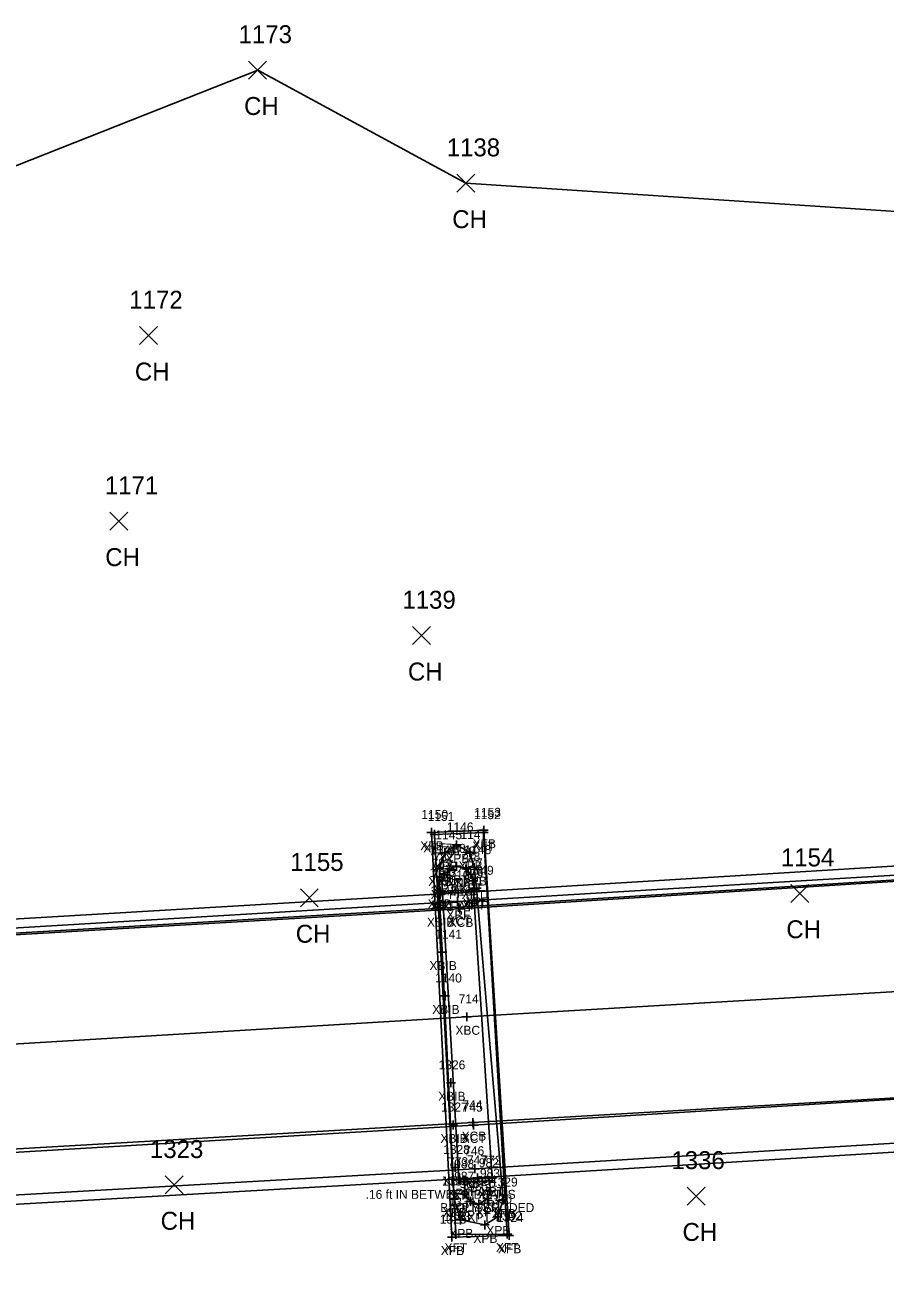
# Model space of a CAD drawing. Extents: x 1715662 to 1717487, y 887396 to 890004.
# Drawn here: x 1717008.3 to 1717104.2, y 888212.7 to 888351.7 of the extents above; entities that cross this region are included whole.
import ezdxf

# ---------------------------------------------------------------- set-up
doc = ezdxf.new("R2010")
doc.units = 0
for name, color, linetype in [('B_A', 7, 'Continuous'), ('B_C', 7, 'Continuous'), ('B_I', 7, 'Continuous'), ('B_TIC', 7, 'Continuous'), ('BDC', 7, 'Continuous'), ('BELB', 7, 'Continuous'), ('BF', 7, 'Continuous'), ('BFT', 7, 'Continuous'), ('BR', 7, 'Continuous'), ('BSUBM', 7, 'Continuous'), ('L_A', 7, 'Continuous'), ('L_I', 7, 'Continuous'), ('L_TIC', 7, 'Continuous'), ('LSOGP', 7, 'Continuous')]:
    doc.layers.add(name, color=color, linetype=linetype)

msp = doc.modelspace()

# ---------------------------------------------------------------- linework, layer by layer
at = {"layer": 'B_TIC'}
for p, q in [((1717053.64, 888261.69), (1717053.72, 888261.69)), ((1717054, 888261.46), (1717054.08, 888261.46)), ((1717059.46, 888261.66), (1717059.54, 888261.66)), ((1717059.48, 888261.92), (1717059.56, 888261.92)), ((1717056.45, 888260.29), (1717056.53, 888260.29)), ((1717055.15, 888259.42), (1717055.23, 888259.42)), ((1717057.94, 888259.45), (1717058.02, 888259.45)), ((1717054.56, 888257.71), (1717054.64, 888257.71)), ((1717055.07, 888256.95), (1717055.14, 888256.95)), ((1717055.66, 888257.62), (1717055.74, 888257.62)), ((1717056.47, 888257.91), (1717056.54, 888257.91)), ((1717057.53, 888257.61), (1717057.61, 888257.61)), ((1717058.05, 888257.01), (1717058.12, 888257.01)), ((1717058.4, 888257.76), (1717058.48, 888257.76)), ((1717054.86, 888256.27), (1717054.94, 888256.27)), ((1717058.31, 888256.28), (1717058.39, 888256.28)), ((1717058.68, 888255.46), (1717058.76, 888255.46)), ((1717054.5, 888255.21), (1717054.58, 888255.21)), ((1717054.86, 888255.09), (1717054.94, 888255.09)), ((1717054.87, 888254.92), (1717054.95, 888254.92)), ((1717056.61, 888254.94), (1717056.69, 888254.94)), ((1717058.36, 888255.09), (1717058.43, 888255.09)), ((1717058.42, 888255.31), (1717058.49, 888255.31)), ((1717054.58, 888253.18), (1717054.66, 888253.18)), ((1717056.56, 888254), (1717056.64, 888254)), ((1717056.7, 888253.34), (1717056.78, 888253.34)), ((1717056.83, 888253.15), (1717056.91, 888253.15)), ((1717054.87, 888248.34), (1717054.94, 888248.34)), ((1717055.17, 888243.46), (1717055.25, 888243.46)), ((1717057.58, 888241.13), (1717057.66, 888241.13)), ((1717055.83, 888233.78), (1717055.9, 888233.78)), ((1717056.07, 888229.08), (1717056.14, 888229.08)), ((1717058.28, 888229.34), (1717058.36, 888229.34)), ((1717058.32, 888229.07), (1717058.4, 888229.07)), ((1717056.31, 888224.35), (1717056.39, 888224.35)), ((1717058.51, 888224.21), (1717058.58, 888224.21)), ((1717056.69, 888222.99), (1717056.77, 888222.99)), ((1717057.37, 888222.75), (1717057.44, 888222.75)), ((1717058.79, 888223.18), (1717058.87, 888223.18)), ((1717060.12, 888222.87), (1717060.19, 888222.87)), ((1717060.42, 888223.16), (1717060.49, 888223.16)), ((1717056.18, 888220.83), (1717056.25, 888220.83)), ((1717057.37, 888221.37), (1717057.45, 888221.37)), ((1717059.88, 888220.9), (1717059.96, 888220.9)), ((1717060.23, 888221.71), (1717060.31, 888221.71)), ((1717061.63, 888220.72), (1717061.71, 888220.72)), ((1717057.99, 888220.56), (1717058.06, 888220.56)), ((1717058.94, 888220.27), (1717059.01, 888220.27)), ((1717056.91, 888218.5), (1717056.98, 888218.5)), ((1717059.6, 888217.94), (1717059.68, 888217.94)), ((1717061.04, 888218.83), (1717061.12, 888218.83)), ((1717055.93, 888216.58), (1717056.01, 888216.58)), ((1717056.37, 888216.89), (1717056.45, 888216.89)), ((1717062.1, 888216.93), (1717062.18, 888216.93)), ((1717062.3, 888216.78), (1717062.38, 888216.78))]:
    msp.add_line(p, q, dxfattribs=at)
for points in [[(1717059.48, 888261.42), (1717059.48, 888262.42)], [(1717053.14, 888261.69), (1717054.14, 888261.69)], [(1717053.5, 888261.46), (1717054.5, 888261.46)], [(1717053.64, 888261.19), (1717053.64, 888262.19)], [(1717054, 888260.96), (1717054, 888261.96)], [(1717058.96, 888261.66), (1717059.96, 888261.66)], [(1717058.98, 888261.92), (1717059.98, 888261.92)], [(1717059.46, 888261.16), (1717059.46, 888262.16)], [(1717055.15, 888258.92), (1717055.15, 888259.92)], [(1717055.95, 888260.29), (1717056.95, 888260.29)], [(1717056.45, 888259.79), (1717056.45, 888260.79)], [(1717057.94, 888258.95), (1717057.94, 888259.95)], [(1717054.56, 888257.21), (1717054.56, 888258.21)], [(1717054.65, 888259.42), (1717055.65, 888259.42)], [(1717056.46, 888257.41), (1717056.46, 888258.41)], [(1717057.44, 888259.45), (1717058.44, 888259.45)], [(1717058.4, 888257.26), (1717058.4, 888258.26)], [(1717054.06, 888257.71), (1717055.06, 888257.71)], [(1717054.56, 888256.95), (1717055.56, 888256.95)], [(1717055.06, 888256.45), (1717055.06, 888257.45)], [(1717055.16, 888257.62), (1717056.16, 888257.62)], [(1717055.66, 888257.12), (1717055.66, 888258.12)], [(1717055.96, 888257.91), (1717056.96, 888257.91)], [(1717057.03, 888257.61), (1717058.03, 888257.61)], [(1717057.53, 888257.11), (1717057.53, 888258.11)], [(1717057.54, 888257.01), (1717058.54, 888257.01)], [(1717057.9, 888257.76), (1717058.9, 888257.76)], [(1717058.04, 888256.51), (1717058.04, 888257.51)], [(1717054.36, 888256.27), (1717055.36, 888256.27)], [(1717054.5, 888254.71), (1717054.5, 888255.71)], [(1717054.86, 888255.77), (1717054.86, 888256.77)], [(1717054.86, 888254.59), (1717054.86, 888255.59)], [(1717056.61, 888254.44), (1717056.61, 888255.44)], [(1717057.81, 888256.28), (1717058.81, 888256.28)], [(1717058.18, 888255.46), (1717059.18, 888255.46)], [(1717058.31, 888255.78), (1717058.31, 888256.78)], [(1717058.35, 888254.59), (1717058.35, 888255.59)], [(1717058.41, 888254.81), (1717058.41, 888255.81)], [(1717058.68, 888254.96), (1717058.68, 888255.96)], [(1717054, 888255.21), (1717055, 888255.21)], [(1717054.36, 888255.09), (1717055.36, 888255.09)], [(1717054.37, 888254.92), (1717055.37, 888254.92)], [(1717054.87, 888254.42), (1717054.87, 888255.42)], [(1717056.11, 888254.94), (1717057.11, 888254.94)], [(1717056.56, 888253.5), (1717056.56, 888254.5)], [(1717057.85, 888255.09), (1717058.85, 888255.09)], [(1717057.91, 888255.31), (1717058.91, 888255.31)], [(1717054.08, 888253.18), (1717055.08, 888253.18)], [(1717054.58, 888252.68), (1717054.58, 888253.68)], [(1717056.06, 888254), (1717057.06, 888254)], [(1717056.2, 888253.34), (1717057.2, 888253.34)], [(1717056.33, 888253.15), (1717057.33, 888253.15)], [(1717056.7, 888252.84), (1717056.7, 888253.84)], [(1717056.83, 888252.65), (1717056.83, 888253.65)], [(1717054.86, 888247.84), (1717054.86, 888248.84)], [(1717054.36, 888248.34), (1717055.36, 888248.34)], [(1717054.67, 888243.46), (1717055.67, 888243.46)], [(1717055.17, 888242.96), (1717055.17, 888243.96)], [(1717057.58, 888240.63), (1717057.58, 888241.63)], [(1717057.08, 888241.13), (1717058.08, 888241.13)], [(1717055.32, 888233.78), (1717056.32, 888233.78)], [(1717055.82, 888233.28), (1717055.82, 888234.28)], [(1717055.57, 888229.08), (1717056.57, 888229.08)], [(1717056.07, 888228.58), (1717056.07, 888229.58)], [(1717057.78, 888229.34), (1717058.78, 888229.34)], [(1717057.82, 888229.07), (1717058.82, 888229.07)], [(1717058.28, 888228.84), (1717058.28, 888229.84)], [(1717058.32, 888228.57), (1717058.32, 888229.57)], [(1717056.31, 888223.85), (1717056.31, 888224.85)], [(1717055.81, 888224.35), (1717056.81, 888224.35)], [(1717056.69, 888222.49), (1717056.69, 888223.49)], [(1717058, 888224.21), (1717059, 888224.21)], [(1717058.5, 888223.71), (1717058.5, 888224.71)], [(1717058.79, 888222.68), (1717058.79, 888223.68)], [(1717060.41, 888222.66), (1717060.41, 888223.66)], [(1717056.19, 888222.99), (1717057.19, 888222.99)], [(1717056.86, 888222.75), (1717057.86, 888222.75)], [(1717057.36, 888222.25), (1717057.36, 888223.25)], [(1717058.29, 888223.18), (1717059.29, 888223.18)], [(1717059.61, 888222.87), (1717060.61, 888222.87)], [(1717059.91, 888223.16), (1717060.91, 888223.16)], [(1717060.11, 888222.37), (1717060.11, 888223.37)], [(1717060.23, 888221.21), (1717060.23, 888222.21)], [(1717055.67, 888220.83), (1717056.67, 888220.83)], [(1717056.17, 888220.33), (1717056.17, 888221.33)], [(1717056.87, 888221.37), (1717057.87, 888221.37)], [(1717057.37, 888220.87), (1717057.37, 888221.87)], [(1717057.99, 888220.06), (1717057.99, 888221.06)], [(1717058.93, 888219.77), (1717058.93, 888220.77)], [(1717059.38, 888220.9), (1717060.38, 888220.9)], [(1717059.73, 888221.71), (1717060.73, 888221.71)], [(1717059.88, 888220.4), (1717059.88, 888221.4)], [(1717061.13, 888220.72), (1717062.13, 888220.72)], [(1717061.63, 888220.22), (1717061.63, 888221.22)], [(1717057.49, 888220.56), (1717058.49, 888220.56)], [(1717058.43, 888220.27), (1717059.43, 888220.27)], [(1717061.04, 888218.33), (1717061.04, 888219.33)], [(1717056.4, 888218.5), (1717057.4, 888218.5)], [(1717056.9, 888218), (1717056.9, 888219)], [(1717059.1, 888217.94), (1717060.1, 888217.94)], [(1717059.6, 888217.44), (1717059.6, 888218.44)], [(1717060.54, 888218.83), (1717061.54, 888218.83)], [(1717055.43, 888216.58), (1717056.43, 888216.58)], [(1717055.87, 888216.89), (1717056.87, 888216.89)], [(1717055.93, 888216.08), (1717055.93, 888217.08)], [(1717056.37, 888216.39), (1717056.37, 888217.39)], [(1717061.6, 888216.93), (1717062.6, 888216.93)], [(1717061.8, 888216.78), (1717062.8, 888216.78)], [(1717062.1, 888216.43), (1717062.1, 888217.43)], [(1717062.3, 888216.28), (1717062.3, 888217.28)]]:
    msp.add_lwpolyline(points, dxfattribs=at)
at = {"layer": 'BDC'}
for points in [[(1717176.59, 888262.23), (1717176.88, 888260.81), (1717116.83, 888257.09), (1717056.7, 888253.34), (1716997.03, 888249.86), (1716937, 888246.31), (1716877.5, 888242.93), (1716877.3, 888244.49)], [(1717176.98, 888262.02), (1717176.87, 888260.51), (1717116.83, 888256.95), (1717056.83, 888253.15), (1716997, 888249.66), (1716937.06, 888246.1), (1716877.42, 888242.56)], [(1716878.98, 888212.69), (1716878.75, 888218.61), (1716938.22, 888221.98), (1716998.22, 888225.49), (1717058.32, 888229.07), (1717118.07, 888232.73), (1717177.98, 888236.21), (1717178.1, 888235.65), (1717178.63, 888230.44)], [(1716878.76, 888218.78), (1716938.25, 888222.24), (1716997.85, 888225.86), (1717058.28, 888229.34), (1717118.15, 888232.86), (1717177.91, 888236.5)]]:
    msp.add_lwpolyline(points, dxfattribs=at)
at = {"layer": 'BELB'}
msp.add_lwpolyline([(1717176.82, 888248.24), (1717117.6, 888244.66), (1717057.58, 888241.13), (1716997.66, 888237.53), (1716937.87, 888233.85), (1716878.26, 888230.51)], dxfattribs=at)
at = {"layer": 'BF'}
for points in [[(1717176.59, 888262.23), (1717116.54, 888258.64), (1717056.61, 888254.94), (1716996.92, 888251.43), (1716937.1, 888247.95), (1716877.3, 888244.49)], [(1716878.98, 888212.69), (1716938.93, 888216.1), (1716998.54, 888219.73), (1717058.79, 888223.18), (1717118.39, 888226.86), (1717178.63, 888230.44)]]:
    msp.add_lwpolyline(points, dxfattribs=at)
at = {"layer": 'BFT'}
for points in [[(1717053.64, 888261.69), (1717059.48, 888261.92), (1717062.3, 888216.78), (1717055.93, 888216.58)], [(1717055.93, 888216.58), (1717053.64, 888261.69)], [(1717054, 888261.46), (1717059.46, 888261.66), (1717062.1, 888216.93), (1717056.37, 888216.89)], [(1717056.37, 888216.89), (1717054, 888261.46)]]:
    msp.add_lwpolyline(points, dxfattribs=at)
at = {"layer": 'BR'}
for points in [[(1717176, 888261.98), (1717175.88, 888261.14), (1717117.06, 888257.61), (1717056.56, 888254), (1716997.02, 888250.41), (1716936.97, 888246.78), (1716878.14, 888243.39), (1716877.96, 888244.41)], [(1716879.62, 888212.9), (1716879.68, 888213.78), (1716938.7, 888217.13), (1716998.52, 888220.76), (1717058.5, 888224.21), (1717118.65, 888227.87), (1717177.58, 888231.53), (1717177.86, 888230.64)]]:
    msp.add_lwpolyline(points, dxfattribs=at)
at = {"layer": 'BSUBM'}
for points in [[(1717054.5, 888255.21), (1717054.56, 888257.71), (1717055.15, 888259.42), (1717056.45, 888260.29), (1717057.94, 888259.45), (1717058.4, 888257.76), (1717058.68, 888255.46)], [(1717058.41, 888255.31), (1717058.31, 888256.28), (1717058.04, 888257.01), (1717057.53, 888257.61), (1717056.46, 888257.91), (1717055.66, 888257.62), (1717055.06, 888256.95), (1717054.86, 888256.27), (1717054.86, 888255.09)], [(1717061.63, 888220.72), (1717058.68, 888255.46)], [(1717056.17, 888220.83), (1717054.5, 888255.21)], [(1717054.86, 888255.09), (1717058.41, 888255.31)], [(1717060.41, 888223.16), (1717056.69, 888222.99), (1717054.87, 888254.92), (1717058.35, 888255.09)], [(1717058.35, 888255.09), (1717060.41, 888223.16)], [(1717060.11, 888222.87), (1717060.23, 888221.71), (1717059.88, 888220.9), (1717058.93, 888220.27), (1717057.99, 888220.56), (1717057.37, 888221.37), (1717057.36, 888222.75)], [(1717057.36, 888222.75), (1717060.11, 888222.87)], [(1717061.63, 888220.72), (1717061.04, 888218.83), (1717059.6, 888217.94), (1717056.9, 888218.5), (1717056.17, 888220.83)]]:
    msp.add_lwpolyline(points, dxfattribs=at)
at = {"layer": 'L_TIC'}
for points in [[(1717033.28, 888345.63), (1717035.28, 888347.63)], [(1717035.28, 888345.63), (1717033.28, 888347.63)], [(1717056.48, 888333.02), (1717058.48, 888335.02)], [(1717058.48, 888333.02), (1717056.48, 888335.02)], [(1717021.11, 888316.04), (1717023.11, 888318.04)], [(1717023.11, 888316.04), (1717021.11, 888318.04)], [(1717017.81, 888295.36), (1717019.81, 888297.36)], [(1717019.81, 888295.36), (1717017.81, 888297.36)], [(1717051.54, 888282.61), (1717053.54, 888284.61)], [(1717053.54, 888282.61), (1717051.54, 888284.61)], [(1717093.71, 888253.89), (1717095.71, 888255.89)], [(1717095.71, 888253.89), (1717093.71, 888255.89)], [(1717039.04, 888253.39), (1717041.04, 888255.39)], [(1717041.04, 888253.39), (1717039.04, 888255.39)], [(1717023.98, 888221.4), (1717025.98, 888223.4)], [(1717025.98, 888221.4), (1717023.98, 888223.4)], [(1717082.14, 888220.16), (1717084.14, 888222.16)], [(1717084.14, 888220.16), (1717082.14, 888222.16)]]:
    msp.add_lwpolyline(points, dxfattribs=at)
at = {"layer": 'LSOGP'}
msp.add_lwpolyline([(1717115.57, 888330.22), (1717057.48, 888334.02), (1717034.29, 888346.63), (1716994.9, 888331.05), (1716971.92, 888329.41), (1716927.78, 888315.88), (1716905.33, 888322.14), (1716871.24, 888333.89), (1716808.97, 888341.31), (1716791.42, 888346.37), (1716790.32, 888340.43), (1716790.15, 888340.32), (1716789.9, 888340.16), (1716789.24, 888334.17), (1716791.29, 888331.62), (1716789.78, 888320.76), (1716788.41, 888319.78), (1716784.01, 888251.37), (1716721.33, 888252.74), (1716722.06, 888265.93), (1716706.46, 888265.74)], dxfattribs=at)

# ---------------------------------------------------------------- texts
at = {"layer": 'B_A'}
for s, p in [('XFB', (1717052.4, 888259.69)), ('XFT', (1717052.74, 888259.46)), ('XFT', (1717058.2, 888259.66)), ('XFB', (1717058.24, 888259.92)), ('XPB', (1717053.89, 888257.42)), ('XPB', (1717055.19, 888258.29)), ('XPB', (1717056.68, 888257.45)), ('XPT', (1717055.18, 888255.91)), ('XPB', (1717053.3, 888255.71)), ('XPT', (1717053.78, 888254.95)), ('XPT', (1717054.38, 888255.62)), ('XPT', (1717056.25, 888255.61)), ('XPT', (1717056.76, 888255.01)), ('XPB', (1717057.14, 888255.76)), ('XPB', (1717053.24, 888253.21)), ('XPT', (1717053.58, 888254.27)), ('XPT', (1717053.58, 888253.09)), ('XPT', (1717057.03, 888254.28)), ('XPT', (1717057.07, 888253.09)), ('XPT', (1717057.14, 888253.31)), ('XPB', (1717057.42, 888253.46)), ('XPT', (1717053.59, 888252.92)), ('XFAT', (1717054.87, 888252.94)), ('XRF', (1717055.32, 888252)), ('XBIB', (1717053.15, 888251.18)), ('XCT', (1717055.42, 888251.34)), ('XCB', (1717055.57, 888251.15)), ('XBIB', (1717053.43, 888246.34)), ('XBIB', (1717053.74, 888241.46)), ('XBC', (1717056.32, 888239.13)), ('XBIB', (1717054.4, 888231.78)), ('XBIB', (1717054.64, 888227.08)), ('XCB', (1717057.01, 888227.34)), ('XCT', (1717057.04, 888227.07)), ('XBIB', (1717054.88, 888222.35)), ('XFAT', (1717057.05, 888221.18)), ('XRF', (1717057.26, 888222.21)), ('XPT', (1717059.14, 888221.16)), ('XPT', (1717055.41, 888220.99)), ('XPT', (1717056.08, 888220.75)), ('XPT', (1717058.83, 888220.87)), ('XPT', (1717058.95, 888219.71)), ('XPB', (1717054.91, 888218.83)), ('XPT', (1717056.09, 888219.37)), ('XPT', (1717056.71, 888218.56)), ('XPT', (1717058.6, 888218.9)), ('XPB', (1717060.37, 888218.72)), ('XPT', (1717057.65, 888218.27)), ('XPB', (1717055.64, 888216.5)), ('XPB', (1717058.33, 888215.94)), ('XPB', (1717059.77, 888216.83)), ('XFB', (1717054.69, 888214.58)), ('XFT', (1717055.11, 888214.89)), ('XFT', (1717060.84, 888214.93)), ('XFB', (1717061.06, 888214.78))]:
    msp.add_text(s, height=1, dxfattribs=at).set_placement(p)
at = {"layer": 'B_C'}
for s, p in [('.16 ft IN BETWEEN BEAMS', (1717046.32, 888220.85)), ('BADLY ERODED', (1717054.63, 888219.37))]:
    msp.add_text(s, height=1, dxfattribs=at).set_placement(p)
at = {"layer": 'B_I'}
for s, p in [('1150', (1717052.53, 888263.19)), ('1151', (1717053.22, 888262.96)), ('1152', (1717058.4, 888263.16)), ('1153', (1717058.42, 888263.42)), ('1146', (1717055.36, 888261.79)), ('1145', (1717054.09, 888260.92)), ('1147', (1717056.88, 888260.95)), ('1144', (1717053.5, 888259.21)), ('781', (1717054.76, 888259.12)), ('780', (1717055.24, 888259.41)), ('779', (1717056.34, 888259.11)), ('1148', (1717057.34, 888259.26)), ('783', (1717053.68, 888257.77)), ('782', (1717053.88, 888258.45)), ('778', (1717056.86, 888258.51)), ('777', (1717057.13, 888257.78)), ('1143', (1717053.44, 888256.71)), ('784', (1717053.68, 888256.59)), ('774', (1717053.69, 888256.42)), ('710', (1717055.67, 888256.44)), ('775', (1717057.17, 888256.59)), ('776', (1717057.21, 888256.81)), ('1149', (1717057.61, 888256.96)), ('1142', (1717053.51, 888254.68)), ('712', (1717055.8, 888254.84)), ('713', (1717055.93, 888254.65)), ('711', (1717055.94, 888255.5)), ('1141', (1717054.08, 888249.84)), ('1140', (1717054.06, 888244.96)), ('714', (1717056.68, 888242.63)), ('1326', (1717054.45, 888235.28)), ('744', (1717057.1, 888230.84)), ('1327', (1717054.72, 888230.58)), ('745', (1717057.14, 888230.57)), ('1328', (1717054.96, 888225.85)), ('746', (1717057.3, 888225.71)), ('773', (1717055.51, 888224.49)), ('988', (1717056.18, 888224.25)), ('747', (1717057.61, 888224.68)), ('982', (1717058.93, 888224.37)), ('772', (1717059.23, 888224.66)), ('987', (1717056.19, 888222.87)), ('983', (1717059.05, 888223.21)), ('1335', (1717054.83, 888222.33)), ('986', (1717056.78, 888222.06)), ('985', (1717057.75, 888221.77)), ('984', (1717058.7, 888222.4)), ('1329', (1717060.28, 888222.22)), ('1334', (1717055.56, 888220)), ('1330', (1717059.65, 888220.33)), ('1333', (1717055.02, 888218.39)), ('1331', (1717058.54, 888219.44)), ('1332', (1717060.75, 888218.43)), ('1324', (1717060.95, 888218.28)), ('1325', (1717054.58, 888218.08))]:
    msp.add_text(s, height=1, dxfattribs=at).set_placement(p)
at = {"layer": 'L_A'}
for p in [(1717032.77, 888341.63), (1717055.97, 888329.02), (1717020.6, 888312.04), (1717017.3, 888291.36), (1717051.03, 888278.61), (1717038.53, 888249.39), (1717093.2, 888249.89), (1717023.47, 888217.4), (1717081.63, 888216.16)]:
    msp.add_text('CH', height=2, dxfattribs=at).set_placement(p)
at = {"layer": 'L_I'}
for s, p in [('1173', (1717032.16, 888349.63)), ('1138', (1717055.35, 888337.02)), ('1172', (1717019.98, 888320.04)), ('1171', (1717017.25, 888299.36)), ('1139', (1717050.41, 888286.61)), ('1154', (1717092.59, 888257.89)), ('1155', (1717037.91, 888257.39)), ('1323', (1717022.28, 888225.4)), ('1336', (1717080.39, 888224.16))]:
    msp.add_text(s, height=2, dxfattribs=at).set_placement(p)

doc.saveas('drawing.dxf')
